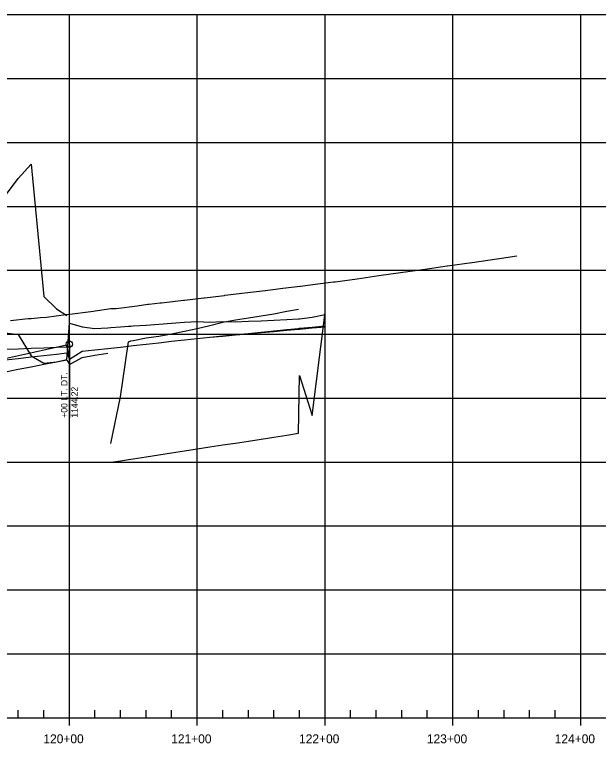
# Model space of a CAD drawing. Extents: x 688474 to 694748, y 765018 to 767373.
# Drawn here: x 692911 to 693367, y 765790 to 766360 of the extents above; entities that cross this region are included whole.
import ezdxf

# ---------------------------------------------------------------- set-up
doc = ezdxf.new("R2010")
doc.units = 0
for name, color, linetype in [('30', 7, 'Continuous'), ('37', 7, 'Continuous'), ('R_Exist Surface', 7, 'Continuous'), ('R_Profile Work Left', 7, 'Continuous'), ('R_Profile Work Right', 7, 'Continuous'), ('R_Vert Alg', 7, 'Continuous'), ('R_Vert Alg Annot', 7, 'Continuous')]:
    doc.layers.add(name, color=color, linetype=linetype)

msp = doc.modelspace()

# ---------------------------------------------------------------- linework, layer by layer
at = {"layer": '37'}
for p, q in [((690853.59, 766359.92), (693453.59, 766359.92)), ((690853.59, 766359.92), (693453.59, 766359.92)), ((692953.59, 765809.92), (692953.59, 766359.92)), ((693053.59, 765809.92), (693053.59, 766359.92)), ((693153.59, 765809.92), (693153.59, 766359.92)), ((693253.59, 765809.92), (693253.59, 766359.92)), ((693353.59, 765809.92), (693353.59, 766359.92)), ((690853.59, 766309.92), (693453.59, 766309.92)), ((690853.59, 766259.92), (693453.59, 766259.92)), ((690853.59, 766209.92), (693453.59, 766209.92)), ((690853.59, 766159.92), (693453.59, 766159.92)), ((690853.59, 766109.92), (693453.59, 766109.92)), ((690853.59, 766059.92), (693453.59, 766059.92)), ((690853.59, 766009.92), (693453.59, 766009.92)), ((690853.59, 765959.92), (693453.59, 765959.92)), ((690853.59, 765909.92), (693453.59, 765909.92)), ((690853.59, 765859.92), (693453.59, 765859.92)), ((692913.59, 765809.92), (692913.59, 765815.92)), ((692933.59, 765809.92), (692933.59, 765815.92)), ((692973.59, 765809.92), (692973.59, 765815.92)), ((692993.59, 765809.92), (692993.59, 765815.92)), ((693013.59, 765809.92), (693013.59, 765815.92)), ((693033.59, 765809.92), (693033.59, 765815.92)), ((693073.59, 765809.92), (693073.59, 765815.92)), ((693093.59, 765809.92), (693093.59, 765815.92)), ((693113.59, 765809.92), (693113.59, 765815.92)), ((693133.59, 765809.92), (693133.59, 765815.92)), ((693173.59, 765809.92), (693173.59, 765815.92)), ((693193.59, 765809.92), (693193.59, 765815.92)), ((693213.59, 765809.92), (693213.59, 765815.92)), ((693233.59, 765809.92), (693233.59, 765815.92)), ((693273.59, 765809.92), (693273.59, 765815.92)), ((693293.59, 765809.92), (693293.59, 765815.92)), ((693313.59, 765809.92), (693313.59, 765815.92)), ((693333.59, 765809.92), (693333.59, 765815.92)), ((690853.59, 765809.92), (693453.59, 765809.92)), ((692953.59, 765803.92), (692953.59, 765809.92)), ((693053.59, 765803.92), (693053.59, 765809.92)), ((693153.59, 765803.92), (693153.59, 765809.92)), ((693253.59, 765803.92), (693253.59, 765809.92)), ((693353.59, 765803.92), (693353.59, 765809.92))]:
    msp.add_line(p, q, dxfattribs=at)
at = {"layer": 'R_Exist Surface'}
msp.add_lwpolyline([(692907.58, 766120.64), (692921.38, 766122.11), (692923.79, 766122.3), (692931.01, 766123.07), (692935.65, 766123.32), (692950.71, 766125.33), (692954.07, 766125.53), (692970.28, 766127.77), (692986.07, 766130), (692987.31, 766130.14), (692988.43, 766129.95), (692990.09, 766130.14), (693006.57, 766132.15), (693014.87, 766133.39), (693015.85, 766133.5), (693024.71, 766134.34), (693025.77, 766134.46), (693042.85, 766136.55), (693043.52, 766136.6), (693058.84, 766138.42), (693059.38, 766138.47), (693074.84, 766140.31), (693075.25, 766140.35), (693090.83, 766142.21), (693106.67, 766144.1), (693106.83, 766144.11), (693106.96, 766144.13), (693120.52, 766145.83), (693120.62, 766145.84), (693134.21, 766147.55), (693134.27, 766147.55), (693147.9, 766149.26), (693147.93, 766149.27), (693160.17, 766150.8), (693161.59, 766150.98), (693161.59, 766150.98), (693178.64, 766153.35), (693178.65, 766153.35), (693195.69, 766155.72), (693195.7, 766155.72), (693212.75, 766158.1), (693212.75, 766158.1), (693229.8, 766160.47), (693229.8, 766160.47), (693230, 766160.5), (693230.09, 766160.51), (693249.17, 766163.27), (693249.3, 766163.29), (693268.54, 766166.07), (693268.81, 766166.11), (693287.91, 766168.87), (693288.33, 766168.93), (693303.59, 766171.14)], dxfattribs=at)
at = {"layer": 'R_Profile Work Left'}
for points in [[(692903.59, 766218.43), (692913.59, 766231.76), (692923.59, 766243.02), (692933.59, 766139.53), (692943.59, 766129.88), (692951.68, 766124.5)], [(692951.68, 766090.04), (692953.59, 766118.58), (692963.59, 766115.66), (692973.59, 766114.26), (692983.59, 766114.9), (692985.98, 766115.06), (692993.59, 766115.56), (692999.77, 766116.13), (693001.68, 766116.25), (693003.59, 766116.38), (693013.59, 766117.04), (693023.59, 766117.86), (693033.59, 766118.54), (693043.59, 766119.34), (693053.59, 766119.75), (693063.59, 766119.33), (693073.59, 766119.75), (693083.59, 766119.62), (693093.59, 766120.13), (693103.59, 766120.35), (693113.59, 766120.94), (693123.59, 766121.4), (693132.89, 766121.99), (693133.59, 766122.04), (693143.59, 766123.16), (693153.59, 766125.3)], [(692903.59, 766098.09), (692913.59, 766098.52), (692923.59, 766098.94), (692933.59, 766099.37), (692943.59, 766099.8), (692951.68, 766100.14), (692953.59, 766090.43), (692963.59, 766096.57), (692973.59, 766097.68), (692983.59, 766098.79), (692985.98, 766099.06), (692993.59, 766099.9), (692999.77, 766100.59), (693001.68, 766100.81), (693003.59, 766101.02), (693013.59, 766102.13), (693023.59, 766103.24), (693033.59, 766104.36), (693043.59, 766105.47), (693053.59, 766106.58), (693063.59, 766107.58), (693073.59, 766108.57), (693083.59, 766109.56), (693093.59, 766110.56), (693103.59, 766111.55), (693113.59, 766112.54), (693123.59, 766113.54), (693132.89, 766114.46), (693133.59, 766114.53), (693143.59, 766115.52), (693153.59, 766116.51)], [(692903.59, 766080.44), (692913.59, 766082.44), (692923.59, 766084.43), (692933.59, 766086.43), (692943.59, 766088.42), (692951.68, 766090.04)], [(692985.98, 766009.72), (692993.59, 766010.9), (692999.77, 766011.85), (693001.68, 766012.15), (693003.59, 766012.44), (693013.59, 766013.99), (693023.59, 766015.53), (693033.59, 766017.08), (693043.59, 766018.62), (693053.59, 766020.17), (693063.59, 766021.71), (693073.59, 766023.26), (693083.59, 766024.8), (693093.59, 766026.35), (693103.59, 766027.89), (693113.59, 766029.44), (693123.59, 766030.98), (693132.89, 766032.42), (693133.59, 766077.62)]]:
    msp.add_lwpolyline(points, dxfattribs=at)
at = {"layer": 'R_Profile Work Right'}
for points in [[(692985.98, 766024.38), (692993.59, 766060.92), (692999.77, 766103.94), (693001.68, 766104.7), (693003.59, 766105.09), (693013.59, 766106.96), (693023.59, 766108.35), (693033.59, 766110.31), (693043.59, 766112.33), (693053.59, 766114.28), (693063.59, 766116.79), (693073.59, 766119.31), (693083.59, 766121.08), (693093.59, 766122.75), (693103.59, 766124.19), (693113.59, 766125.92), (693123.59, 766127.81), (693132.89, 766129.5)], [(693133.59, 766077.62), (693143.59, 766046.36), (693153.59, 766126.87)], [(692883.27, 766108.04), (692883.59, 766108.18), (692893.59, 766110.91), (692895.28, 766110.92), (692903.59, 766110.95), (692913.59, 766109.67), (692923.59, 766093.03)], [(692903.59, 766089.89), (692913.59, 766091), (692923.59, 766092.11), (692933.59, 766093.23), (692943.59, 766094.34), (692951.68, 766095.24), (692953.59, 766090.43), (692963.59, 766096.57), (692973.59, 766097.68), (692983.59, 766098.79), (692985.98, 766099.06), (692993.59, 766099.9), (692999.77, 766100.59), (693001.68, 766100.81), (693003.59, 766101.02), (693013.59, 766102.13), (693023.59, 766103.24), (693033.59, 766104.36), (693043.59, 766105.47), (693053.59, 766106.58), (693063.59, 766107.49), (693073.59, 766108.4), (693083.59, 766109.31), (693093.59, 766110.22), (693103.59, 766111.13), (693113.59, 766112.04), (693123.59, 766112.95), (693132.89, 766113.79), (693133.59, 766113.86), (693143.59, 766114.77), (693153.59, 766115.67)], [(692923.59, 766093.03), (692933.59, 766087.14), (692943.59, 766088.35), (692951.68, 766089.78), (692953.59, 766086.25), (692963.59, 766091.66), (692973.59, 766093.39), (692983.59, 766095.15)], [(692985.98, 766009.72), (692993.59, 766010.9), (692999.77, 766011.85), (693001.68, 766012.15), (693003.59, 766012.44), (693013.59, 766013.99), (693023.59, 766015.53), (693033.59, 766017.08), (693043.59, 766018.62), (693053.59, 766020.17), (693063.59, 766021.71), (693073.59, 766023.26), (693083.59, 766024.8), (693093.59, 766026.35), (693103.59, 766027.89), (693113.59, 766029.44), (693123.59, 766030.98), (693132.89, 766032.42)]]:
    msp.add_lwpolyline(points, dxfattribs=at)
at = {"layer": 'R_Vert Alg'}
msp.add_line((692503.54, 766001.76), (692951.23, 766101.59), dxfattribs=at)
msp.add_circle((692953.59, 766102.12), 2.5, dxfattribs=at)
at = {"layer": 'R_Vert Alg Annot'}
msp.add_line((692953.59, 766102.12), (692953.59, 766044.62), dxfattribs=at)

# ---------------------------------------------------------------- texts
at = {"layer": '30'}
for s, p in [('120+00', (692933.28, 765789.92)), ('121+00', (693033.28, 765789.92)), ('122+00', (693133.28, 765789.92)), ('123+00', (693233.28, 765789.92)), ('124+00', (693333.28, 765789.92))]:
    msp.add_text(s, height=7, dxfattribs=at).set_placement(p)
at = {"layer": 'R_Vert Alg Annot'}
for s, p in [('+00 LT. DT.', (692952.09, 766044.62)), ('1144.22', (692960.09, 766044.62))]:
    msp.add_text(s, height=5, rotation=90, dxfattribs=at).set_placement(p)

doc.saveas('drawing.dxf')
